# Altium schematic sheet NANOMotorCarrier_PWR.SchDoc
size A3
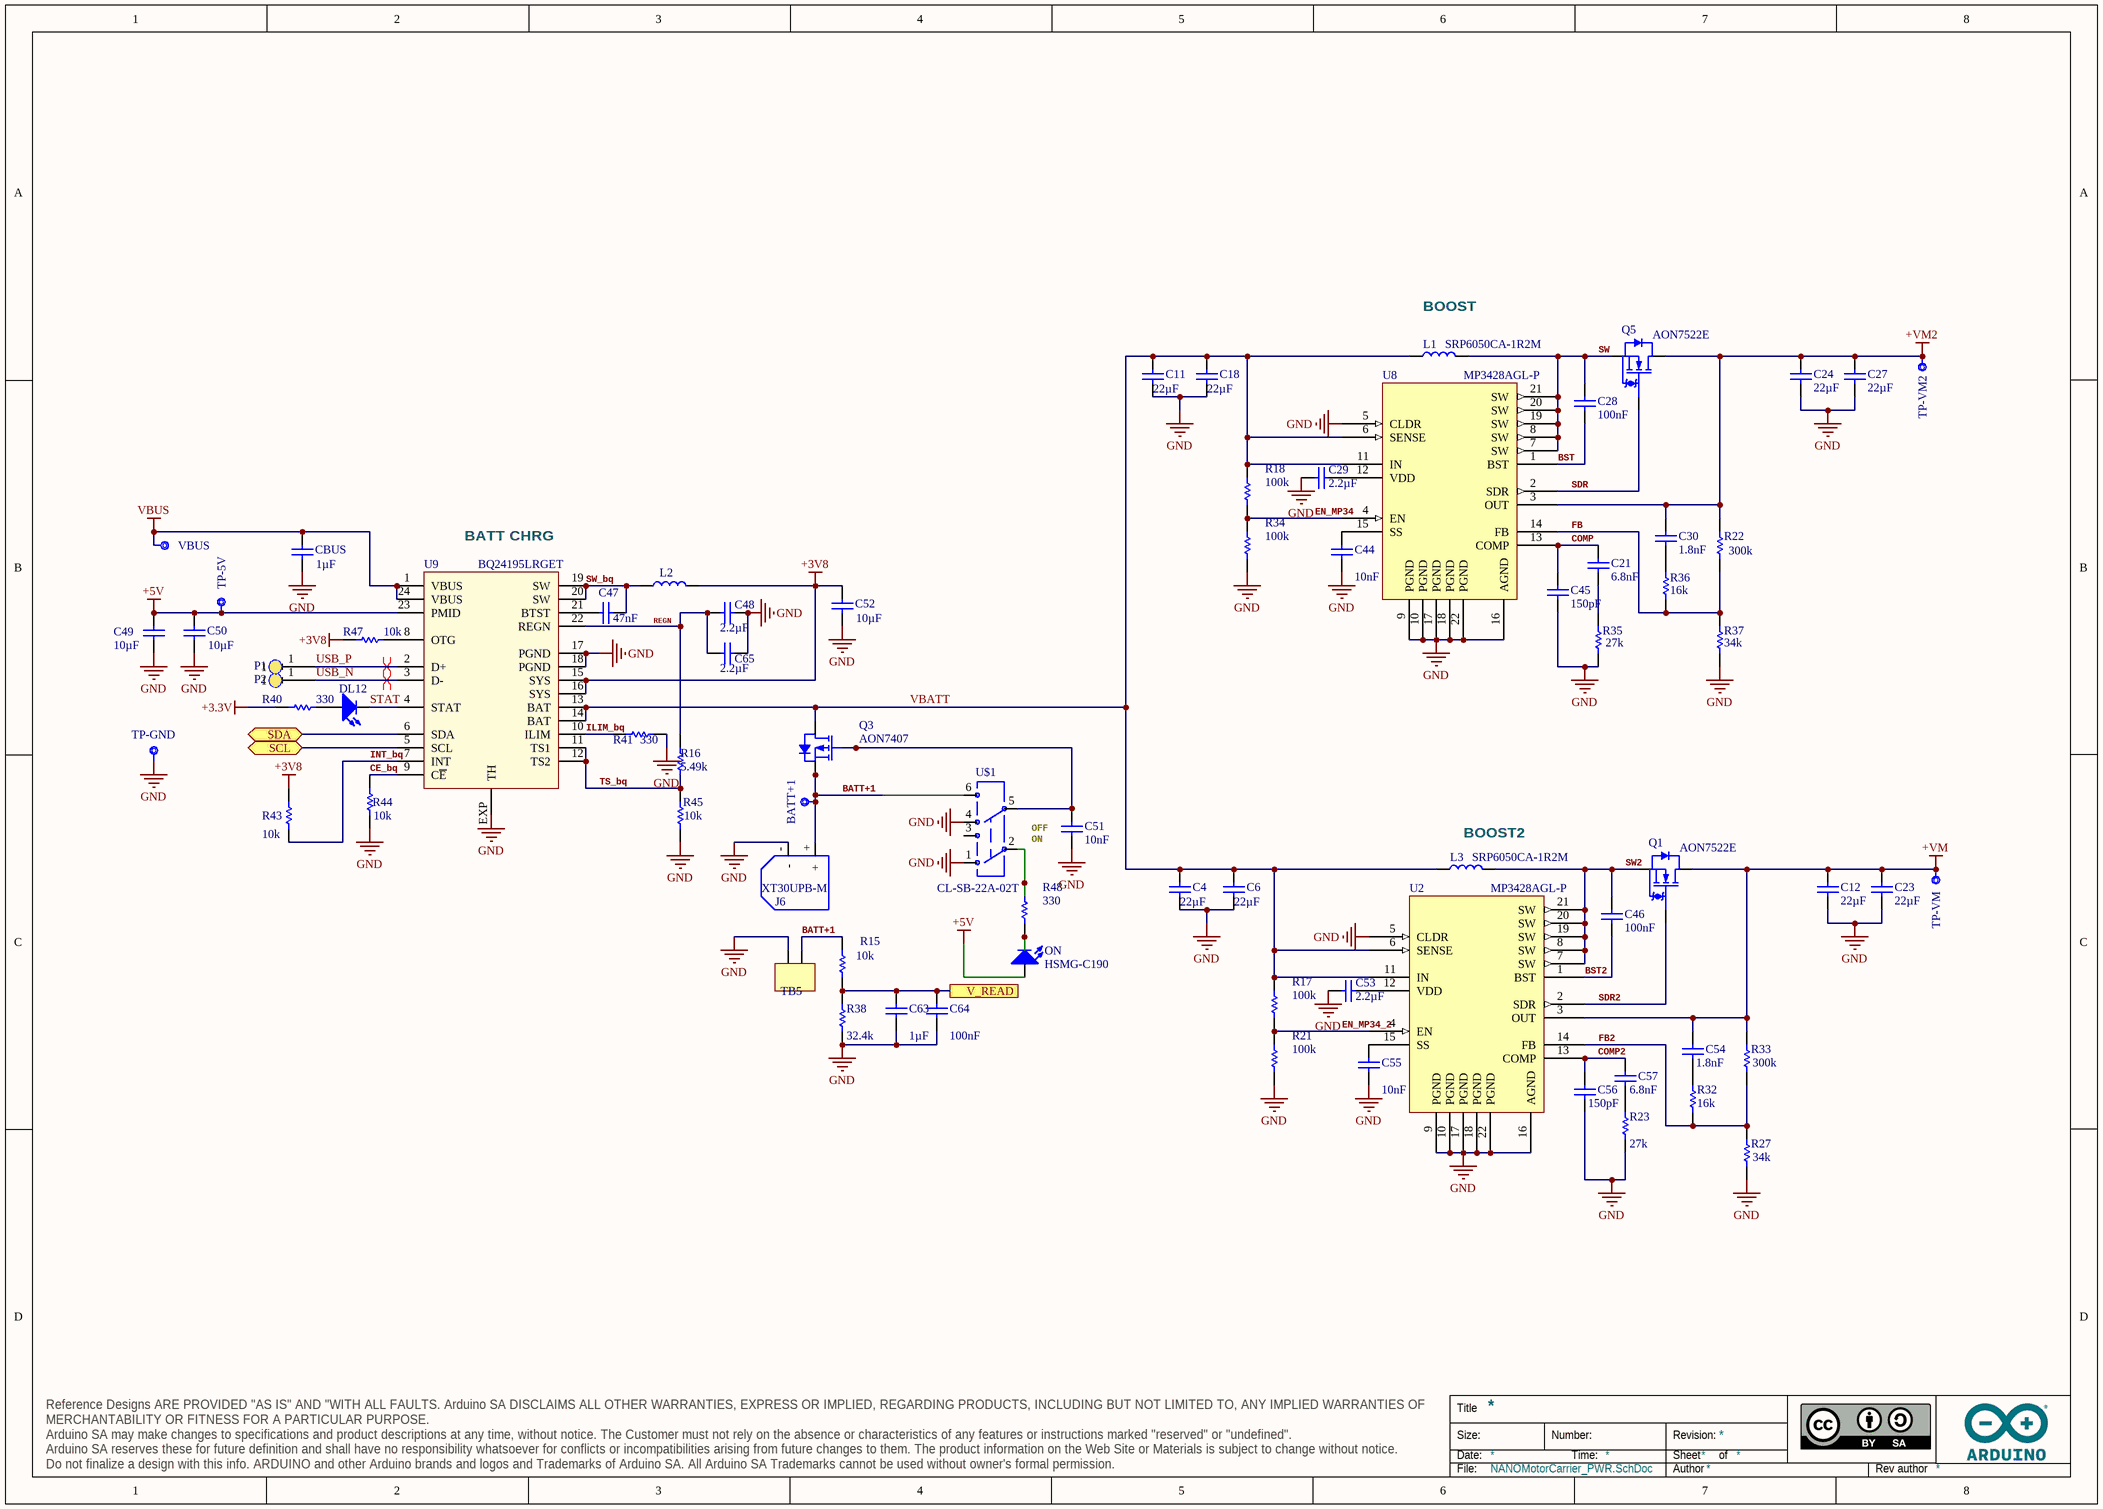
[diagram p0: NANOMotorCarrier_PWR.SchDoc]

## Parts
BATT+1  CMP-018-0006-A.4  [TP-1.27MM]  (value not drawn)  (no BOM)
C4  value 22µF  [CAP-0603]  (hidden comment: CL10A226MO7JZNC)
C6  value 22µF  [CAP-0603]  (hidden comment: CL10A226MO7JZNC)
C11  value 22µF  [CAP-0603]  (hidden comment: CL10A226MO7JZNC)
C12  value 22µF  [CAP-1210]  (hidden comment: C1210C226K3PACTU)
C18  value 22µF  [CAP-0603]  (hidden comment: CL10A226MO7JZNC)
C21  value 6.8nF  [CAP-0402]  (hidden comment: CC0402KRX7R9BB682)
C23  value 22µF  [CAP-1210]  (hidden comment: C1210C226K3PACTU)
C24  value 22µF  [CAP-1210]  (hidden comment: C1210C226K3PACTU)
C27  value 22µF  [CAP-1210]  (hidden comment: C1210C226K3PACTU)
C28  value 100nF  [CAP-0402]  (hidden comment: GRM155R61H104KE19D)
C29  value 2.2µF  [CAP-0402]  (hidden comment: CC0402MRX5R5BB225)
C30  value 1.8nF  [CAP-0402]  (hidden comment: C0402C182J3GAC7867)
C44  value 10nF  [CAP-0402]  (hidden comment: C0402C103K5RACTU)
C45  value 150pF  [CAP-0402]  (hidden comment: GRM1555C1H151FA01D)
C46  value 100nF  [CAP-0402]  (hidden comment: GRM155R61H104KE19D)
C47  value 47nF  [CAP-0402]  (hidden comment: GRM155R61H473KE14D)
C48  value 2.2µF  [CAP-0402]  (hidden comment: CC0402MRX5R5BB225)
C49  value 10µF  [CAP-1206]  (hidden comment: GRM31CR61H106KA12L)
C50  value 10µF  [CAP-1206]  (hidden comment: GRM31CR61H106KA12L)
C51  value 10nF  [CAP-0402]  (hidden comment: C0402C103K5RACTU)
C52  value 10µF  [CAP-1206]  (hidden comment: GRM31CR61H106KA12L)
C53  value 2.2µF  [CAP-0402]  (hidden comment: CC0402MRX5R5BB225)
C54  value 1.8nF  [CAP-0402]  (hidden comment: C0402C182J3GAC7867)
C55  value 10nF  [CAP-0402]  (hidden comment: C0402C103K5RACTU)
C56  value 150pF  [CAP-0402]  (hidden comment: GRM1555C1H151FA01D)
C57  value 6.8nF  [CAP-0402]  (hidden comment: CC0402KRX7R9BB682)
C63  value 1µF  [CAP-0603]  (hidden comment: C0603C105K3PACTU)
C64  value 100nF  [CAP-0402]  (hidden comment: GRM155R61H104KE19D)
C65  value 2.2µF  [CAP-0402]  (hidden comment: CC0402MRX5R5BB225)
CBUS  value 1µF  [CAP-0603]  (hidden comment: C0603C105K3PACTU)
DL12  KPT-1608SECK  [LEDC1608X80N-AK]  (value not drawn)
J6  XT30UPB-M  [XT30UPB-M-Footprint-1]
L1  SRP6050CA-1R2M  [INDP6466X48N]
L2  SRP4020TA-2R2M  [SRP4020]  (value not drawn)
L3  SRP6050CA-1R2M  [INDP6466X48N]
ON  HSMG-C190  [LEDC1608X80N-AK]
P1  0929-7-15-20-7X-14-11-0  [New footprint 1]  (value not drawn)
P2  0929-7-15-20-7X-14-11-0  [New footprint 1]  (value not drawn)
Q1  AON7522E  [DFN8]
Q3  AON7407  [DFN8]
Q5  AON7522E  [DFN8]
R15  value 10k  [RES-0402]  (hidden comment: CRCW040210K0FKED)
R16  value 5.49k  [RES-0402]  (hidden comment: CRCW04025K49FKED)
R17  value 100k  [RES-0402]  (hidden comment: CRCW0402100KFKEDC)
R18  value 100k  [RES-0402]  (hidden comment: CRCW0402100KFKEDC)
R21  value 100k  [RES-0402]  (hidden comment: CRCW0402100KFKEDC)
R22  value 300k  [RES-0402]  (hidden comment: RC0402FR-07300KL)
R23  value 27k  [RES-0402]  (hidden comment: CRCW040227K0JNED)
R27  value 34k  [RES-0402]  (hidden comment: RC0402FR-0734KL)
R32  value 16k  [RES-0402]  (hidden comment: CRCW040216K0JNED)
R33  value 300k  [RES-0402]  (hidden comment: RC0402FR-07300KL)
R34  value 100k  [RES-0402]  (hidden comment: CRCW0402100KFKEDC)
R35  value 27k  [RES-0402]  (hidden comment: CRCW040227K0JNED)
R36  value 16k  [RES-0402]  (hidden comment: CRCW040216K0JNED)
R37  value 34k  [RES-0402]  (hidden comment: RC0402FR-0734KL)
R38  value 32.4k  [RES-0402]  (hidden comment: CRCW040232K4FKED)
R40  value 330  [RES-0402]  (hidden comment: CRCW0402330RJNED)
R41  value 330  [RES-0402]  (hidden comment: CRCW0402330RJNED)
R43  value 10k  [RES-0402]  (hidden comment: CRCW040210K0FKED)
R44  value 10k  [RES-0402]  (hidden comment: CRCW040210K0FKED)
R45  value 10k  [RES-0402]  (hidden comment: CRCW040210K0FKED)
R47  value 10k  [RES-0402]  (hidden comment: CRCW040210K0FKED)
R48  value 330  [RES-0402]  (hidden comment: CRCW0402330RJNED)
TB5  MK125002GO  [MK125002GO]  (value not drawn)
TP-5V  CMP-018-0006-A.4  [TP-1.27MM]  (value not drawn)  (no BOM)
TP-GND  CMP-018-0006-A.4  [TP-1.27MM]  (value not drawn)  (no BOM)
TP-VM  CMP-018-0006-A.4  [TP-1.27MM]  (value not drawn)  (no BOM)
TP-VM2  CMP-018-0006-A.4  [TP-1.27MM]  (value not drawn)  (no BOM)
U2  MP3428AGL-P  [QFN50P300X400X100-20N]
U8  MP3428AGL-P  [QFN50P300X400X100-20N]
U9  BQ24195LRGET  [VQFN24]
U$1  CL-SB-22A-02T  [CL-SB-22A]
VBUS  CMP-018-0006-A.4  [TP-1.27MM]  (value not drawn)  (no BOM)

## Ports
SCL (bidir), SDA (bidir), V_READ

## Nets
+3.3V: R40.2
+3V8: C52.2 L2.2 R43.1 R47.1 U9.15(SYS) U9.16(SYS)
+5V: C49.2 C50.2 ON.A TP-5V.X U9.23(PMID)
+VM: C12.2 C23.2 C54.1 Q1.3(D) R33.2 TP-VM.X U2.3(OUT)
+VM2: C24.2 C27.2 C30.1 Q5.3(D) R22.2 TP-VM2.X U8.3(OUT)
GND: C4.1 C6.1 C11.1 C12.1 C18.1 C23.1 C24.1 C27.1 C29.1 C44.1 C45.2 C48.2 C49.1 C50.1 C51.1 C52.1 C53.1 C55.1 C56.2 C63.2 C64.1 C65.2 CBUS.2 J6.- R21.1 R23.1 R27.1 R34.1 R35.1 R37.1 R38.1 R41.2 R44.1 R45.1 TB5.2 TP-GND.X U2.5(CLDR) U2.9(PGND) U2.10(PGND) U2.16(AGND) U2.17(PGND) U2.18(PGND) U2.22(PGND) U8.5(CLDR) U8.9(PGND) U8.10(PGND) U8.16(AGND) U8.17(PGND) U8.18(PGND) U8.22(PGND) U9.17(PGND) U9.18(PGND) U9.EXP(TH) U$1.1 U$1.4
VBUS: CBUS.1 U9.1(VBUS) U9.24(VBUS) VBUS.X
BATT+1: BATT+1.X J6.+ Q3.1(S) Q3.2(S) Q3.3(S) R15.2 TB5.1 U$1.6
BST: C28.2 U8.1(BST)
BST2: C46.2 U2.1(BST)
CE_bq: R44.2 U9.9(C~{E})
COMP: C21.2 C45.1 U8.13(COMP)
COMP2: C56.1 C57.2 U2.13(COMP)
EN_MP34: R18.1 R34.2 U8.4(EN)
EN_MP34_2: R17.1 R21.2 U2.4(EN)
FB: R22.1 R36.1 R37.2 U8.14(FB)
FB2: R27.2 R32.1 R33.1 U2.14(FB)
ILIM_bq: R41.1 U9.10(ILIM)
INT_bq: R43.2 U9.7(INT)
REGN: C48.1 C65.1 R16.2 U9.22(REGN)
SCL: U9.5(SCL) ; port SCL
SDA: U9.6(SDA) ; port SDA
SDR: Q5.1(G) U8.2(SDR)
SDR2: Q1.1(G) U2.2(SDR)
STAT: DL12.C U9.4(STAT)
SW: C28.1 L1.2 Q5.2(S) U8.7(SW) U8.8(SW) U8.19(SW) U8.20(SW) U8.21(SW)
SW2: C46.1 L3.2 Q1.2(S) U2.7(SW) U2.8(SW) U2.19(SW) U2.20(SW) U2.21(SW)
SW_bq: C47.2 L2.1 U9.19(SW) U9.20(SW)
TS_bq: R16.1 R45.2 U9.11(TS1) U9.12(TS2)
USB_N: P2.1 U9.3(D-)
USB_P: P1.1 U9.2(D+)
V_READ: C63.1 C64.2 R15.1 R38.2 ; port V_READ
VBATT: C4.2 C6.2 C11.2 C18.2 L1.1 L3.1 Q3.5(D) R17.2 R18.2 U2.6(SENSE) U2.11(IN) U8.6(SENSE) U8.11(IN) U9.13(BAT) U9.14(BAT)
NetC21_1: C21.1 R35.2
NetC29_2: C29.2 U8.12(VDD)
NetC30_2: C30.2 R36.2
NetC44_2: C44.2 U8.15(SS)
NetC47_1: C47.1 U9.21(BTST)
NetC51_2: C51.2 Q3.4(G) U$1.5
NetC53_2: C53.2 U2.12(VDD)
NetC54_2: C54.2 R32.2
NetC55_2: C55.2 U2.15(SS)
NetC57_1: C57.1 R23.2
NetDL12_A: DL12.A R40.1
NetON_C: ON.C R48.1
NetR47_2: R47.2 U9.8(OTG)
NetR48_2: R48.2 U$1.2

Not connected (* = marked no-connect by the designer): U$1 3

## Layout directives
differential pair: USB_N, USB_P

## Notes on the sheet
- (near L1) BOOST
- (near U9) BATT CHRG
- (near C51) OFF
  ON
- (near L3) BOOST2

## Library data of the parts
BATT+1 TP-5V TP-GND TP-VM TP-VM2 VBUS = UT0014-A.2: Test point 1.27mm
C4 C6 C11 C18 = C0072-A.1: CAP CHIP 0603 22UF X5R 16V 20%; Manufacturer: Samsung; Voltage: 6.3V; Code Arduino: C0072
C12 C23 C24 C27 = C0064-A.3: CAP CHIP 1210 22uF 25V X5R 10%; Manufacturer: KEMET; Code Arduino: 0167
C21 C57 = C0089-A.4: CAP CHIP 0402 6.9nF 50V X7R 10%; Manufacturer: Yageo; Code Arduino: C0089
C28 C46 C64 = C0015-A.3: CAP CHIP 0402 100nF 50V X5R 10%; Manufacturer: Murata; Code Arduino: A5141
C29 C48 C53 C65 = C0076-A.2: CAP CHIP 0402 2.2UF 6.3V 20%; Manufacturer: Yageo; Code Arduino: A5334; Dielectric: X5R
C30 C54 = C0073-A.1: CAP CHIP 0402 1.8NF 25V C0G 5%; Manufacturer: KEMET; Code Arduino: C0073
C44 C51 C55 = C0009-A.3: CAP CHIP 0402 10nF 50V X7R 10%; Manufacturer: KEMET; Code Arduino: 0165
C45 C56 = C0074-A.1: CAP CHIP 0402 150PF 50V C0G 1%; Manufacturer: Murata; Code Arduino: C0074
C47 = C0036-A.3: CAP CHIP 0402 47nF 50V X5R 10%; Manufacturer: Murata; Code Arduino: 2216
C49 C50 C52 = C0061-A.3: CAP CHIP 1206 10uF 50V X5R 10%; Manufacturer: Murata; Code Arduino: 2227
C63 CBUS = C0044-A.3: CAP CHIP 0603 1uF 25V X5R 10%; Manufacturer: KEMET; Code Arduino: 0006
DL12 = L0006-A.3: LED SMD 0603 ORANGE601 250mcd 120^; Manufacturer: Kingbright; Code Arduino: 2207
J6 = J0002-A.3: CONN LIPO BATTERY; Manufacturer: AMASS; Code Arduino: A5516
L1 L3 = I0036-A.3: 1.2µH Shielded Wirewound Inductor 18A 5.83mOhm Max Nonstandard (6.60mm x 6.40mm); Manufacturer: Bourns Inc.; Code Arduino: I0036
L2 = I0017-A.3: IND FIXED 2.2UH 4A 61 MOHM SMD; Manufacturer: Bourns; Code Arduino: 2218
ON = L0009-A.3: LED SMD 0603 GREEN/568 15mcd 120^; Manufacturer: Broadcom; Code Arduino: 2204
P1 P2 = J0054-A.3: CONTACT SPRING LOADED T/H GOLD; Manufacturer: Mill-Max Manufacturing Corp; Code Arduino: A5562
Q1 Q5 = T0016-A.3: MOSFET N-CH 30V 21A 8DFN; Manufacturer: Alpha & Omega Semiconductor; Continuous Drain Current (ID): 34A; Code Arduino: A5561; Rds On Max: 4mR
Q3 = T0007-A.4: MOSFET P-CH 20V 14.5A 8DFN; Manufacturer: Alpha & Omega Semiconductor Inc.; Code Arduino: 2251; Device Type: Mosfet P-CH SMD; Power Dissipation: 29W; Gate to Source Voltage (Vgs): 8V; Continuous Drain Current (ID): 40A; Rds On Max: 9.5mR; Number of Elements: 1
R15 R43-R45 R47 = R0003-A.3: RES CHIP 0402 10K 1% 1/16W; Manufacturer: Vishay; Code Arduino: 0136; Power: 63mW
R16 = R0014-A.3: RES CHIP 0402 5K49 1% 1/16W; Manufacturer: Vishay; Code Arduino: 2197; Power: 63mW
R17 R18 R21 R34 = R0001-A.3: RES CHIP 0402 100K 1% 1/16W; Manufacturer: Vishay; Power: 63mW; Code Arduino: 0134
R22 R33 = R0171-A.4: RES CHIP 0402 300K 1% 1/16W; Manufacturer: Yageo; Voltage Rating: 50V; Temperature Coefficient: 100ppm/°C; Code Arduino: R0171; Power Rating: 63mW; Resistance: 300kR
R23 R35 = R0068-A.4: RES CHIP 0402 27K 5% 1/16W; Manufacturer: Vishay; Power: 63mW; Code Arduino: R0068
R27 R37 = R0172-A.5: RES SMD 34K OHM 1% 1/16W 0402; Manufacturer: Yageo; Power Rating: 62.5mW; Temperature Coefficient: 100ppm/°C; Voltage Rating: 50V; Code Arduino: R0172; Resistance: 34kR; Max Power Dissipation: 63mW
R32 R36 = R0138-A.1: RES CHIP 0402 16K 1/16W 1%; Manufacturer: Vishay; Tolerance: 5%; Power: 63mW; Code Arduino: R0138
R38 = R0074-A.5: RES CHIP 0402 32K4 1% 1/16W; Manufacturer: Vishay; Code Arduino: R0074; Power: 63mW
R40 R41 R48 = R0017-A.5: RES CHIP 0402 330R 5% 1/16W; Manufacturer: Vishay; Code Arduino: 2229; Power: 63mW
TB5 = J0012-A.4: CONN MORS.CS 2v p3,5 10A aLING.VER; Manufacturer: Adimpex; Code Arduino: 2341
U2 U8 = U0013-A.5: IC BOOST CONV INPUT DISCONNECT 10A 600KHZ; Manufacturer: Monolithic Power Systems; Code Arduino: U0013; Device Type: Boost Converter IC
U9 = U0044-A.4: IC BATT.CHRG.CTRL. VQFN24; Manufacturer: Texas Instruments; Code Arduino: 2201
U$1 = S0004-A.2: SWITCH SLIDE DPDT 200MA; Manufacturer: Nidec Copal Electronics; Code Arduino: 2247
